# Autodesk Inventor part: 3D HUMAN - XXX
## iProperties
Category: PART
Company: Cross Bros.
Shininess: 64.0
Length Units: 11272
Angle Units: 11279
Time Units: 11290
Mass Units: 11286
Length Display Precision: 3
Angle Display Precision: 2
Compacted: True
Part Number: 3D HUMAN - XXX
Document SubType Name: Modeling
Created: 2003-03
Designer: MVF
Catalog Web Link: www.crossbros.com
Density: 0.0
Volumn: 0.0
Area: 0.0
PropertySet Name: Model Information
Control State: 0
Master: False
Checked Out: False
Author: MVF
Title: iMike
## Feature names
1. Revolution1
2. Split1
